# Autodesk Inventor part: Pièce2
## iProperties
Shininess: 64.0
Length Units: 11269
Angle Units: 11279
Time Units: 11290
Mass Units: 11283
Length Display Precision: 3
Angle Display Precision: 2
Compacted: True
Part Number: Pièce2
Document SubType Name: Modeling
Created: 2004-06
Material: Par défaut
Designer: administrateur
Density: 0.0
Volumn: 0.0
Area: 0.0
PropertySet Name: Model Information
Control State: 0
Master: False
Checked Out: False
Author: administrateur
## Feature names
1. Extrusion1
2. Extrusion2
3. Extrusion3
4. Balayage2
5. Réseau rectangulaire2 [Rectangular Pattern]
